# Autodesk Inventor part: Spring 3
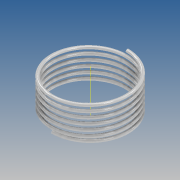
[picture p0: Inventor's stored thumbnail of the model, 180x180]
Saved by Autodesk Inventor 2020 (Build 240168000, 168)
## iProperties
Created: 2019-10
Part Number: Spring 3
Material: Generic
Document SubType Name: Modeling
Designer: yello
Density: 1 g/cm^3
Appearance: Default
Author: yello
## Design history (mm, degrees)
sketch "Sketch1"
  geometry: L1 (0, 0)-(8, 0); L2 (0, 0)-(0, 3.1); C1 r 0.125 at (0, 3.1)
  constraints: 4 end point, 1 centre point, 1 coincident, 1 horizontal, 1 vertical
  dimensions: "d0" = 8 distance of L1.start L1.end; "d1" = 3.1 distance of L1.start L2.end; "d2" = 0.25 diameter of C1
coil "Coil1" sketch "Sketch1" pitch "d3" = 0.45; turns "d5" = 6; dims "d4" = 10, "d6" = 0, angle "d7" = 90 deg, angle "d8" = 90 deg, "d9" = 0, "d10" = 0
body "Solid1"
